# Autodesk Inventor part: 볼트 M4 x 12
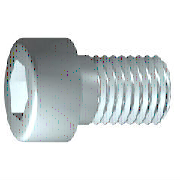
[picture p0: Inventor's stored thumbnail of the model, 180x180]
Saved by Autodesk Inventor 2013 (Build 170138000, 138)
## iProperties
IsCustomPart: 0
Created: 2012-02
Part Number: 볼트 M4 x 12
Material: 강철, 연강
Description: 6각 소켓 머리 캡 나사
Document SubType Name: Modeling
Standard: ISO 4762
Designer: mduedu
Standard Revision: Fourth edition 2004-03-01
Standards Organization: ISO
Language: ko-KR
Size Designation: M4 x 12
Categories: <MemberInstance><Categories><Category DisplayName="조임쇠" InternalName="e4da775c-781d-43d5-af7c-5136215cf5a6" Mnemonic="FSTN"><Category DisplayName="볼트" InternalN
Density: 7.75 g/cm^3
Author: mduedu
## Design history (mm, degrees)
sketch "스케치1"
  geometry: L1 (-1, 0)-(12, 0); L2 (12, 0)-(12, 2); L3 (12, 2)-(1.75, 2); L4 (1.75, 2)-(1.32, 2); L5 (1.32, 2)-(0, 2); L6 (0, 2)-(0, 3.5); L7 (0, 3.5)-(-4, 3.5); L8 (-4, 3.5)-(-4, 1.732); L9 (-4, 1.732)-(-2, 1.732); L10 (-2, 1.732)-(-1, 0); L11 (-7.2, 0)-(15.2, 0) reference; L12 (0, -0.7)-(0, 4.2) reference; L13 (1.75, 2)-(0, 2)
  constraints: 22 end point, 6 parallel, 2 collinear, 2 perpendicular, 1 horizontal, 1 point on line
  dimensions: "d1" = 10.25 distance from line of L3.end L2 (= GEL); "d2" = 0.42952 distance of L4.end L3.end (computed from GAL); "d3" = 4 distance between parallel lines of L8 L6 (= KOH); "d4" = 2 distance of L8.end L9.end (= INTI); "d5" = 60 deg angle of L10 L1; "d6" = 4 diameter of L3 L1 (= GD); "d7" = 4 diameter of L5 L1 (= BDM); "d8" = 3.4641 diameter of L9 L1 (= 1.1547 x SW); "d9" = 7 diameter of L7 L1 (= KOD); "d26" = 12 distance between parallel lines of L12 L2 (= NLG)
revolve "본체" sketch "스케치1" stored, may be unused: angle "d10" = 90 deg
sketch "스케치2"
  geometry: L1 (0, -4.9)-(0, 4.9) reference; L2 (-4.9, 0)-(4.9, 0) reference; L3 (1.732, 0)-(0.866, -1.5); L4 (0.866, -1.5)-(-0.866, -1.5); L5 (-0.866, -1.5)-(-1.732, 0); L6 (-1.732, 0)-(-0.866, 1.5); L7 (-0.866, 1.5)-(0.866, 1.5); L8 (0.866, 1.5)-(1.732, 0); 2 further points
  constraints: 12 end point, 1 coincident, 1 horizontal alignment, 1 point on line, 12 other
extrude "슬롯" join sketch "스케치2" stored distance "d11" = 10; taper "d12" = 0 deg
workplane "Work Plane1"
fillet "Fillet2" dims "d30" = 0.1 (= R)
body "Solid1"
fillet "모깎기1" dims "d17" = 0.4 (= RR)
feature "스레드" dims "d13" = 10.25 (= GEL), "d14" = 0
chamfer "모따기1" distance "d15" = 0.42941 (= -0.5 x SPD + 0.5 x GD); stored, may be unused: second distance "d16" = 0.42941 (= GUL), angle "d27" = 45 deg
other parameters: "GD" = 4 [user parameter; used in 2 equation terms], "NLG" = 12 [user parameter; used in 1 equation term], "GEL" = 10.25 [user parameter; used in 2 equation terms], "KOD" = 7 [user parameter; used in 1 equation term], "KOH" = 4 [user parameter; used in 1 equation term], "INTI" = 2 [user parameter; used in 1 equation term], "GAL" = 0.42941 (= 0.61345 x PTC) [user parameter; used in 1 equation term], "GUL" = 0.42941 (= 0.61345 x PTC) [user parameter; used in 1 equation term], "BDM" = 4 (= NND) [user parameter; used in 1 equation term], "SW" = 3 [user parameter; used in 2 equation terms], "RR" = 0.4 [user parameter; used in 1 equation term], "SPD" = 3.14117 (= NND - 1.2269 x PTC) [user parameter; used in 1 equation term], "d19" = 0, "d28" = 0, "d29" = 0, "R" = 0.1 [user parameter; used in 1 equation term], "TOA" = 30 deg [user parameter], "GD1" = 3.14117 (= THREADDIA - 1.2269 x PTC) [user parameter], "THREADDIA" = 4 [user parameter; used in 1 equation term], "FAWI" = 45 deg [user parameter], "TPU" = 14.28571 (computed from PTC) [user parameter], "PTC" = 0.7 [user parameter; used in 5 equation terms], "NND" = 4 [user parameter; used in 2 equation terms], "E0" = 3.465 (= 1.155 x SW) [user parameter]
